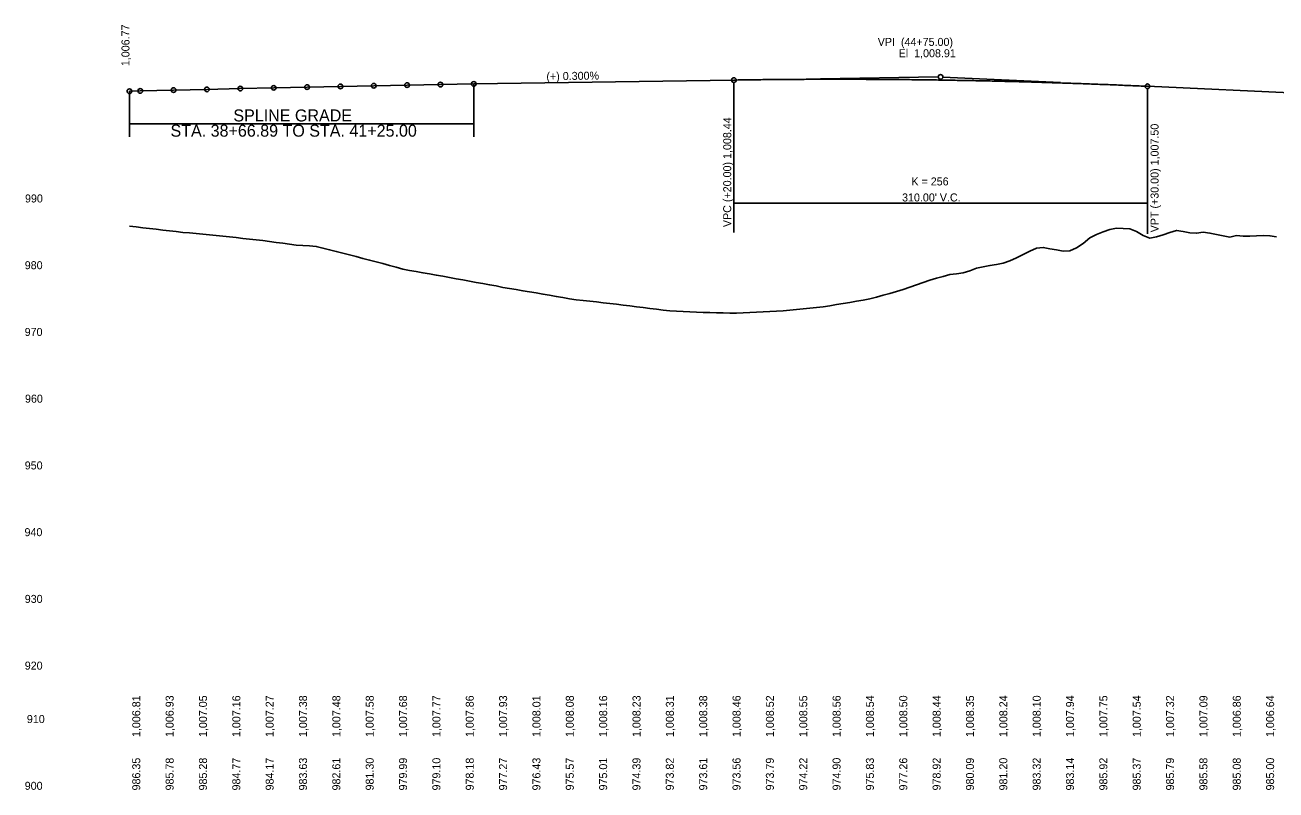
# Model space of a CAD drawing. Extents: x 126 to 16976848, y 7 to 12562190.
# Drawn here: x 16972970 to 16973908, y 12561617 to 12562190 of the extents above; entities that cross this region are included whole.
import ezdxf

# ---------------------------------------------------------------- set-up
doc = ezdxf.new("R2010")
doc.units = 0
for name, color, linetype in [('ANNOT_CONTOUR', 7, 'Continuous'), ('CLS_Shear_Line', 7, 'Continuous'), ('RD_EX_Conc-ZZ', 7, 'Continuous'), ('RD_HC_CL_50', 7, 'Continuous'), ('RD_HC_Points', 7, 'Continuous'), ('RD_HC_TX_Sta20', 7, 'Continuous'), ('RD_HC_TX_Sta50', 7, 'Continuous'), ('RD_PD_ConcMed', 7, 'Continuous'), ('RD_PD_SuperShp1', 7, 'Continuous')]:
    doc.layers.add(name, color=color, linetype=linetype)

msp = doc.modelspace()

# ---------------------------------------------------------------- linework, layer by layer
at = {"layer": 'CLS_Shear_Line'}
for p, q in [((16973501.51, 12562034.97), (16973501.51, 12562147.49)), ((16973811.51, 12562034.09), (16973811.51, 12562142.78)), ((16973501.51, 12562057.03), (16973811.51, 12562057.03))]:
    msp.add_line(p, q, dxfattribs=at)
for centre in [(16973501.51, 12562149.24), (16973811.51, 12562144.53)]:
    msp.add_circle(centre, 1.75, dxfattribs=at)
at = {"layer": 'RD_EX_Conc-ZZ'}
for p, q in [((16973566.52, 12562150.22), (16973654.76, 12562151.54)), ((16973746.41, 12562147.48), (16973658.25, 12562151.49))]:
    msp.add_line(p, q, dxfattribs=at)
for centre in [(16973131.51, 12562142.84), (16973156.51, 12562143.4), (16973181.51, 12562143.93), (16973206.51, 12562144.45), (16973231.51, 12562144.94), (16973256.51, 12562145.42), (16973281.51, 12562145.88), (16973306.51, 12562146.32), (16973656.51, 12562151.57), (16973048.4, 12562140.87), (16973056.51, 12562141.07), (16973081.51, 12562141.68), (16973106.51, 12562142.27)]:
    msp.add_circle(centre, 1.75, dxfattribs=at)
at = {"layer": 'RD_HC_Points'}
for points in [[(16973048.4, 12562039.89), (16973053.4, 12562039.2), (16973058.4, 12562038.56), (16973063.4, 12562038), (16973068.4, 12562037.44), (16973073.4, 12562036.86), (16973078.4, 12562036.28), (16973083.4, 12562035.68), (16973088.4, 12562035.13), (16973093.4, 12562034.67), (16973098.4, 12562034.2), (16973103.4, 12562033.72), (16973108.4, 12562033.24), (16973113.4, 12562032.74), (16973118.4, 12562032.23), (16973123.4, 12562031.71), (16973128.4, 12562031.19), (16973133.4, 12562030.65), (16973138.4, 12562030.11), (16973143.4, 12562029.57), (16973148.4, 12562028.97), (16973153.4, 12562028.29), (16973158.4, 12562027.61), (16973163.4, 12562026.92), (16973168.4, 12562026.22), (16973173.4, 12562025.57), (16973178.4, 12562025.32), (16973183.4, 12562025.05), (16973188.4, 12562024.65), (16973193.4, 12562023.4), (16973198.4, 12562022.14), (16973203.4, 12562020.87), (16973208.4, 12562019.58), (16973213.4, 12562018.29), (16973218.4, 12562016.98), (16973223.4, 12562015.67), (16973228.4, 12562014.36), (16973233.4, 12562013.04), (16973238.4, 12562011.71), (16973243.4, 12562010.37), (16973248.4, 12562009.02), (16973253.4, 12562007.66), (16973258.4, 12562006.53), (16973263.4, 12562005.7), (16973268.4, 12562004.84), (16973273.4, 12562003.97), (16973278.4, 12562003.09), (16973283.4, 12562002.2), (16973288.4, 12562001.3), (16973293.4, 12562000.38), (16973298.4, 12561999.46), (16973303.4, 12561998.52), (16973308.4, 12561997.58), (16973313.4, 12561996.71), (16973318.4, 12561995.86), (16973323.4, 12561994.99), (16973328.4, 12561993.87), (16973333.4, 12561993.04), (16973338.4, 12561992.23), (16973343.4, 12561991.41), (16973348.4, 12561990.57), (16973353.4, 12561989.73), (16973358.4, 12561988.88), (16973363.4, 12561988.01), (16973368.4, 12561987.14), (16973373.4, 12561986.25), (16973378.4, 12561985.35), (16973383.4, 12561984.58), (16973388.4, 12561984.05), (16973393.4, 12561983.51), (16973398.4, 12561982.97), (16973403.4, 12561982.41), (16973408.4, 12561981.84), (16973413.4, 12561981.25), (16973418.4, 12561980.63), (16973423.4, 12561979.98), (16973428.4, 12561979.35), (16973433.4, 12561978.72), (16973438.4, 12561978.11), (16973443.4, 12561977.5), (16973448.4, 12561976.9), (16973453.4, 12561976.3), (16973458.4, 12561976), (16973463.4, 12561975.74), (16973468.4, 12561975.52), (16973473.4, 12561975.32), (16973478.4, 12561975.18), (16973483.4, 12561975.05), (16973488.4, 12561974.92), (16973493.4, 12561974.8), (16973498.4, 12561974.69), (16973503.4, 12561974.72), (16973508.4, 12561974.92), (16973513.4, 12561975.13), (16973518.4, 12561975.35), (16973523.4, 12561975.58), (16973528.4, 12561975.82), (16973533.4, 12561976.06), (16973538.4, 12561976.31), (16973543.4, 12561976.8), (16973548.4, 12561977.29)], [(16973548.4, 12561977.29), (16973553.4, 12561977.8), (16973558.4, 12561978.31), (16973563.4, 12561978.83), (16973568.4, 12561979.36), (16973573.4, 12561980.18), (16973578.4, 12561981.01), (16973583.4, 12561981.84), (16973588.4, 12561982.69), (16973593.4, 12561983.54), (16973598.4, 12561984.4), (16973603.4, 12561985.32), (16973608.4, 12561986.69), (16973613.4, 12561988.06), (16973618.4, 12561989.44), (16973623.4, 12561990.83), (16973628.4, 12561992.25), (16973633.4, 12561994), (16973638.4, 12561995.77), (16973643.4, 12561997.54), (16973648.4, 12561999.32), (16973653.4, 12562000.77), (16973658.4, 12562002.17), (16973663.4, 12562003.61), (16973668.4, 12562004.16), (16973673.4, 12562004.71), (16973678.4, 12562006.24), (16973683.4, 12562008.24), (16973688.4, 12562009.36), (16973693.4, 12562010.22), (16973698.4, 12562011.09), (16973703.4, 12562012), (16973708.4, 12562013.68), (16973713.4, 12562016.09), (16973718.4, 12562018.51), (16973723.4, 12562020.94), (16973728.4, 12562023.23), (16973733.4, 12562023.85), (16973738.4, 12562022.9), (16973743.4, 12562021.96), (16973748.4, 12562021.02), (16973753.4, 12562021.34), (16973758.4, 12562023.58), (16973763.4, 12562026.7), (16973768.4, 12562031.03), (16973773.4, 12562033.62), (16973778.4, 12562035.46), (16973783.4, 12562037.31), (16973788.4, 12562038.18), (16973793.4, 12562038.1), (16973798.4, 12562037.68), (16973803.4, 12562035.68), (16973808.4, 12562032.75), (16973813.4, 12562030.8), (16973818.4, 12562031.76), (16973823.4, 12562033.35), (16973828.4, 12562034.99), (16973833.4, 12562036.57), (16973838.4, 12562035.71), (16973843.4, 12562034.85), (16973848.4, 12562034.48), (16973853.4, 12562035.38), (16973858.4, 12562034.63), (16973863.4, 12562033.57), (16973868.4, 12562032.51), (16973873.4, 12562031.65), (16973878.4, 12562032.81), (16973883.4, 12562032.21), (16973888.4, 12562032.33), (16973893.4, 12562032.54), (16973898.4, 12562032.76), (16973903.4, 12562032.6), (16973908.4, 12562031.7)]]:
    msp.add_lwpolyline(points, dxfattribs=at)
at = {"layer": 'RD_HC_TX_Sta20'}
for p, q in [((16973306.51, 12562106.67), (16973306.51, 12562146.32)), ((16973048.4, 12562106.67), (16973048.4, 12562140.87)), ((16973048.4, 12562116.37), (16973306.51, 12562116.37))]:
    msp.add_line(p, q, dxfattribs=at)
at = {"layer": 'RD_PD_ConcMed'}
for p, q in [((16973206.51, 12562144.45), (16973231.51, 12562144.94)), ((16973231.51, 12562144.94), (16973256.51, 12562145.42)), ((16973256.51, 12562145.42), (16973281.51, 12562145.88)), ((16973281.51, 12562145.88), (16973306.51, 12562146.32)), ((16973306.51, 12562146.32), (16973501.51, 12562149.24)), ((16973811.51, 12562144.53), (16974086.51, 12562132.03)), ((16973048.4, 12562140.87), (16973056.51, 12562141.07)), ((16973056.51, 12562141.07), (16973081.51, 12562141.68)), ((16973081.51, 12562141.68), (16973106.51, 12562142.27)), ((16973106.51, 12562142.27), (16973131.51, 12562142.84)), ((16973131.51, 12562142.84), (16973156.51, 12562143.4)), ((16973156.51, 12562143.4), (16973181.51, 12562143.93)), ((16973181.51, 12562143.93), (16973206.51, 12562144.45))]:
    msp.add_line(p, q, dxfattribs=at)
msp.add_spline([(16973501.51, 12562149.24), (16973507.71, 12562149.33), (16973513.91, 12562149.42), (16973520.11, 12562149.49), (16973526.31, 12562149.56), (16973532.51, 12562149.62), (16973538.71, 12562149.67), (16973544.91, 12562149.71), (16973551.11, 12562149.75), (16973557.31, 12562149.78), (16973563.51, 12562149.8), (16973569.71, 12562149.81), (16973575.91, 12562149.82), (16973582.11, 12562149.82), (16973588.31, 12562149.81), (16973594.51, 12562149.8), (16973600.71, 12562149.77), (16973606.91, 12562149.74), (16973613.11, 12562149.7), (16973619.31, 12562149.66), (16973625.51, 12562149.61), (16973631.71, 12562149.54), (16973637.91, 12562149.48), (16973644.11, 12562149.4), (16973650.31, 12562149.32), (16973656.51, 12562149.23), (16973662.71, 12562149.13), (16973668.91, 12562149.02), (16973675.11, 12562148.91), (16973681.31, 12562148.79), (16973687.51, 12562148.66), (16973693.71, 12562148.53), (16973699.91, 12562148.38), (16973706.11, 12562148.23), (16973712.31, 12562148.07), (16973718.51, 12562147.91), (16973724.71, 12562147.74), (16973730.91, 12562147.55), (16973737.11, 12562147.37), (16973743.31, 12562147.17), (16973749.51, 12562146.97), (16973755.71, 12562146.76), (16973761.91, 12562146.54), (16973768.11, 12562146.31), (16973774.31, 12562146.08), (16973780.51, 12562145.84), (16973786.71, 12562145.59), (16973792.91, 12562145.34), (16973799.11, 12562145.07), (16973805.31, 12562144.8), (16973811.51, 12562144.53)], degree=3, dxfattribs=at)

# ---------------------------------------------------------------- texts
at = {"layer": 'ANNOT_CONTOUR'}
for s, p in [('986.35', (16973056.49, 12561617.03)), ('985.78', (16973081.49, 12561617.03)), ('985.28', (16973106.49, 12561617.03)), ('984.77', (16973131.49, 12561617.03)), ('984.17', (16973156.49, 12561617.03)), ('983.63', (16973181.49, 12561617.03)), ('982.61', (16973206.49, 12561617.03)), ('981.30', (16973231.49, 12561617.03)), ('979.99', (16973256.49, 12561617.03)), ('979.10', (16973281.49, 12561617.03)), ('978.18', (16973306.49, 12561617.03)), ('977.27', (16973331.49, 12561617.03)), ('976.43', (16973356.49, 12561617.03)), ('975.57', (16973381.49, 12561617.03)), ('975.01', (16973406.49, 12561617.03)), ('974.39', (16973431.49, 12561617.03)), ('973.82', (16973456.49, 12561617.03)), ('973.61', (16973481.49, 12561617.03)), ('973.56', (16973506.49, 12561617.03)), ('973.79', (16973531.49, 12561617.03)), ('974.22', (16973556.49, 12561617.03)), ('974.90', (16973581.49, 12561617.03)), ('975.83', (16973606.49, 12561617.03)), ('977.26', (16973631.49, 12561617.03)), ('978.92', (16973656.49, 12561617.03)), ('980.09', (16973681.49, 12561617.03)), ('981.20', (16973706.49, 12561617.03)), ('983.32', (16973731.49, 12561617.03)), ('983.14', (16973756.49, 12561617.03)), ('985.92', (16973781.49, 12561617.03)), ('985.37', (16973806.49, 12561617.03)), ('985.79', (16973831.49, 12561617.03)), ('985.58', (16973856.49, 12561617.03)), ('985.08', (16973881.49, 12561617.03)), ('985.00', (16973906.49, 12561617.03))]:
    msp.add_text(s, height=6, rotation=90, dxfattribs=at).set_placement(p)
at = {"layer": 'CLS_Shear_Line'}
for s, p in [('VPC (+20.00) 1,008.44', (16973499.51, 12562039.06)), ('VPT (+30.00) 1,007.50', (16973819.89, 12562035.14))]:
    msp.add_text(s, height=6, rotation=90, dxfattribs=at).set_placement(p)
for s, p in [('K = 256', (16973634.6, 12562070.28)), ("310.00' V.C.", (16973627.58, 12562058.28))]:
    msp.add_text(s, height=6, dxfattribs=at).set_placement(p)
at = {"layer": 'RD_EX_Conc-ZZ'}
msp.add_text('1,006.77', height=6, rotation=90, dxfattribs=at).set_placement((16973048.4, 12562159.62))
for s, p in [('VPI  (44+75.00)', (16973609.36, 12562174.82)), ('El  1,008.91', (16973625.05, 12562166.32))]:
    msp.add_text(s, height=6, dxfattribs=at).set_placement(p)
at = {"layer": 'RD_HC_CL_50'}
for s, p in [('1,006.81', (16973056.51, 12561657.03)), ('1,006.93', (16973081.51, 12561657.03)), ('1,007.05', (16973106.51, 12561657.03)), ('1,007.16', (16973131.51, 12561657.03)), ('1,007.27', (16973156.51, 12561657.03)), ('1,007.38', (16973181.51, 12561657.03)), ('1,007.48', (16973206.51, 12561657.03)), ('1,007.58', (16973231.51, 12561657.03)), ('1,007.68', (16973256.51, 12561657.03)), ('1,007.77', (16973281.51, 12561657.03)), ('1,007.86', (16973306.51, 12561657.03)), ('1,007.93', (16973331.51, 12561657.03)), ('1,008.01', (16973356.51, 12561657.03)), ('1,008.08', (16973381.51, 12561657.03)), ('1,008.16', (16973406.51, 12561657.03)), ('1,008.23', (16973431.51, 12561657.03)), ('1,008.31', (16973456.51, 12561657.03)), ('1,008.38', (16973481.51, 12561657.03)), ('1,008.46', (16973506.51, 12561657.03)), ('1,008.52', (16973531.51, 12561657.03)), ('1,008.55', (16973556.51, 12561657.03)), ('1,008.56', (16973581.51, 12561657.03)), ('1,008.54', (16973606.51, 12561657.03)), ('1,008.50', (16973631.51, 12561657.03)), ('1,008.44', (16973656.51, 12561657.03)), ('1,008.35', (16973681.51, 12561657.03)), ('1,008.24', (16973706.51, 12561657.03)), ('1,008.10', (16973731.51, 12561657.03)), ('1,007.94', (16973756.51, 12561657.03)), ('1,007.75', (16973781.51, 12561657.03)), ('1,007.54', (16973806.51, 12561657.03)), ('1,007.32', (16973831.51, 12561657.03)), ('1,007.09', (16973856.51, 12561657.03)), ('1,006.86', (16973881.51, 12561657.03)), ('1,006.64', (16973906.51, 12561657.03))]:
    msp.add_text(s, height=6, rotation=90, dxfattribs=at).set_placement(p)
at = {"layer": 'RD_HC_TX_Sta20'}
for s, p in [('SPLINE GRADE', (16973126.3, 12562118.22)), ('STA. 38+66.89 TO STA. 41+25.00', (16973079.17, 12562106.81))]:
    msp.add_text(s, height=9, dxfattribs=at).set_placement(p)
at = {"layer": 'RD_HC_TX_Sta50'}
for s, p in [('990', (16972970.08, 12562057.53)), ('980', (16972969.9, 12562007.53)), ('970', (16972969.84, 12561957.53)), ('960', (16972970.08, 12561907.53)), ('950', (16972969.9, 12561857.53)), ('940', (16972969.72, 12561807.53)), ('930', (16972969.9, 12561757.53)), ('920', (16972969.9, 12561707.53)), ('910', (16972971.48, 12561667.53)), ('900', (16972969.89, 12561617.53))]:
    msp.add_text(s, height=6, dxfattribs=at).set_placement(p)
at = {"layer": 'RD_PD_SuperShp1'}
msp.add_text('(+) 0.300%', height=6, rotation=0.85937, dxfattribs=at).set_placement((16973361, 12562149.04))

doc.saveas('drawing.dxf')
